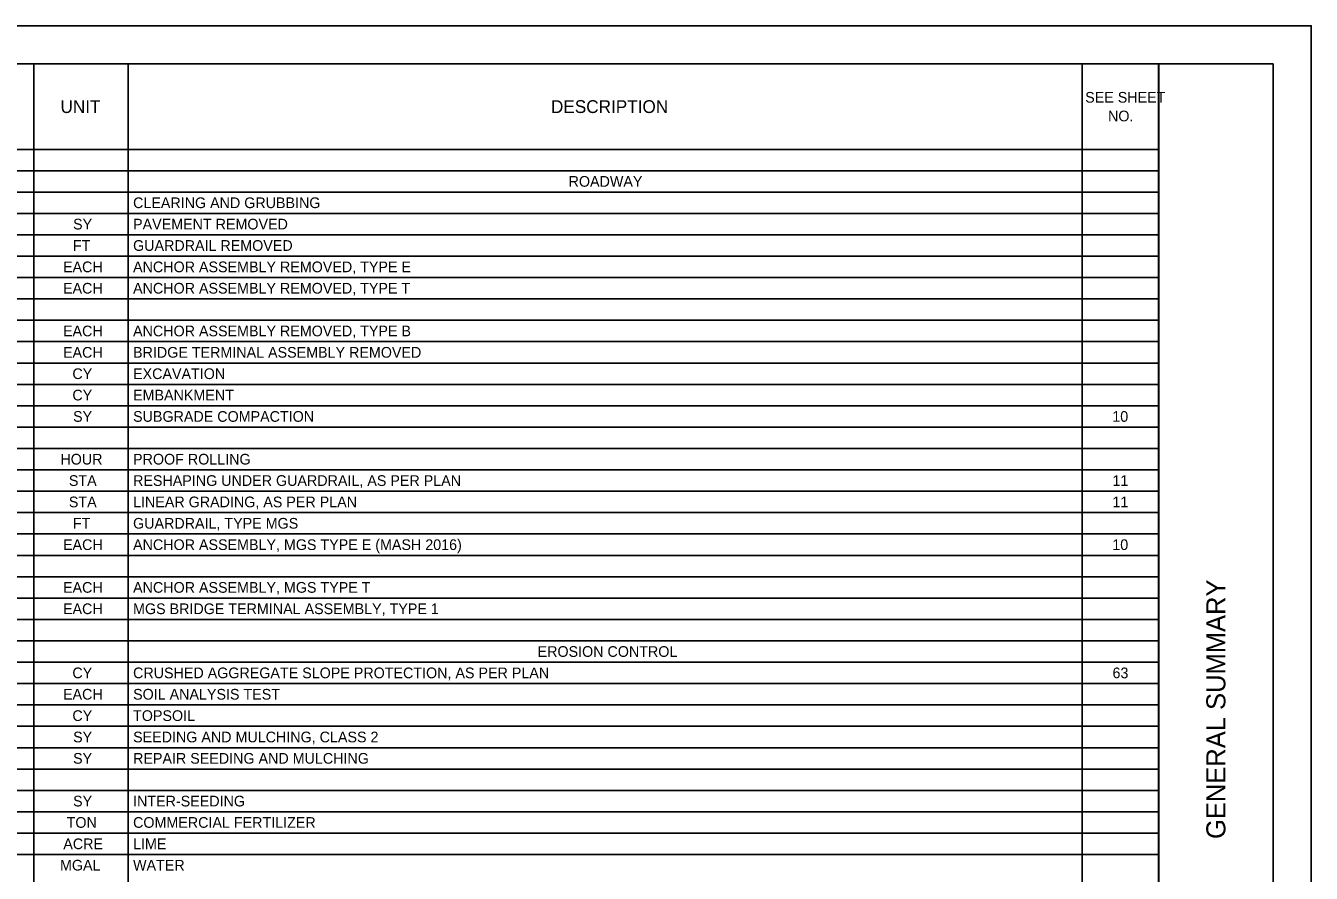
# Model space of a CAD drawing. Extents: x 0 to 34, y 0 to 22.
# Drawn here: x 17.16 to 34, y 10.89 to 22 of the extents above; entities that cross this region are included whole.
import ezdxf

# ---------------------------------------------------------------- set-up
doc = ezdxf.new("R2010")
doc.units = 0
for name, color, linetype in [('SH_Border', 7, 'Continuous'), ('SH_Cut_Line', 7, 'Continuous'), ('SH_Data', 7, 'Continuous'), ('SH_Text', 7, 'Continuous')]:
    doc.layers.add(name, color=color, linetype=linetype)

msp = doc.modelspace()

# ---------------------------------------------------------------- linework, layer by layer
at = {"layer": 'SH_Border'}
msp.add_line((32, 0.5), (32, 21.5), dxfattribs=at)
msp.add_lwpolyline([(1.5, 21.5), (33.5, 21.5), (33.5, 0.5), (1.5, 0.5)], close=True, dxfattribs=at)
at = {"layer": 'SH_Cut_Line'}
msp.add_lwpolyline([(0, 0), (34, 0), (34, 22), (0, 22)], close=True, dxfattribs=at)
at = {"layer": 'SH_Data'}
for p, q in [((1.5, 21.5), (32.004, 21.5)), ((17.262, 21.5), (17.262, 0.5)), ((18.498, 21.5), (18.498, 0.5)), ((30.999, 21.5), (30.999, 0.5)), ((32.004, 21.5), (32.004, 0.5)), ((1.5, 20.38), (32.004, 20.38)), ((1.5, 20.1), (32.004, 20.1)), ((1.5, 19.82), (32.004, 19.82)), ((1.5, 19.54), (32.004, 19.54)), ((1.5, 19.26), (32.004, 19.26)), ((1.5, 18.98), (32.004, 18.98)), ((1.5, 18.7), (32.004, 18.7)), ((1.5, 18.42), (32.004, 18.42)), ((1.5, 18.14), (32.004, 18.14)), ((1.5, 17.86), (32.004, 17.86)), ((1.5, 17.58), (32.004, 17.58)), ((1.5, 17.3), (32.004, 17.3)), ((1.5, 17.02), (32.004, 17.02)), ((1.5, 16.74), (32.004, 16.74)), ((1.5, 16.46), (32.004, 16.46)), ((1.5, 16.18), (32.004, 16.18)), ((1.5, 15.9), (32.004, 15.9)), ((1.5, 15.62), (32.004, 15.62)), ((1.5, 15.34), (32.004, 15.34)), ((1.5, 15.06), (32.004, 15.06)), ((1.5, 14.78), (32.004, 14.78)), ((1.5, 14.5), (32.004, 14.5)), ((1.5, 14.22), (32.004, 14.22)), ((1.5, 13.94), (32.004, 13.94)), ((1.5, 13.66), (32.004, 13.66)), ((1.5, 13.38), (32.004, 13.38)), ((1.5, 13.1), (32.004, 13.1)), ((1.5, 12.82), (32.004, 12.82)), ((1.5, 12.54), (32.004, 12.54)), ((1.5, 12.26), (32.004, 12.26)), ((1.5, 11.98), (32.004, 11.98)), ((1.5, 11.7), (32.004, 11.7)), ((1.5, 11.42), (32.004, 11.42)), ((1.5, 11.14), (32.004, 11.14))]:
    msp.add_line(p, q, dxfattribs=at)

# ---------------------------------------------------------------- texts
msp.add_text('GENERAL SUMMARY', height=0.25, rotation=90, dxfattribs=at).set_placement((32.875, 11.344))
at = {"layer": 'SH_Text'}
for s, height, p in [('SEE SHEET ', 0.14, (31.038, 20.992)), ('UNIT', 0.168, (17.613, 20.856)), ('DESCRIPTION', 0.168, (24.039, 20.856)), ('NO.', 0.14, (31.337, 20.747)), ('ROADWAY', 0.14, (24.27, 19.89)), ('CLEARING AND GRUBBING', 0.14, (18.564, 19.61)), ('SY', 0.14, (17.778, 19.33)), ('PAVEMENT REMOVED', 0.14, (18.564, 19.33)), ('FT', 0.14, (17.776, 19.05)), ('GUARDRAIL REMOVED', 0.14, (18.564, 19.05)), ('EACH', 0.14, (17.646, 18.77)), ('ANCHOR ASSEMBLY REMOVED, TYPE E', 0.14, (18.564, 18.77)), ('EACH', 0.14, (17.646, 18.49)), ('ANCHOR ASSEMBLY REMOVED, TYPE T', 0.14, (18.564, 18.49)), ('EACH', 0.14, (17.646, 17.93)), ('ANCHOR ASSEMBLY REMOVED, TYPE B', 0.14, (18.564, 17.93)), ('EACH', 0.14, (17.646, 17.65)), ('BRIDGE TERMINAL ASSEMBLY REMOVED', 0.14, (18.564, 17.65)), ('CY', 0.14, (17.769, 17.37)), ('EXCAVATION', 0.14, (18.564, 17.37)), ('CY', 0.14, (17.769, 17.09)), ('EMBANKMENT', 0.14, (18.564, 17.09)), ('SY', 0.14, (17.778, 16.81)), ('SUBGRADE COMPACTION', 0.14, (18.564, 16.81)), ('10', 0.14, (31.393, 16.81)), ('HOUR', 0.14, (17.612, 16.25)), ('PROOF ROLLING', 0.14, (18.564, 16.25)), ('STA', 0.14, (17.723, 15.97)), ('RESHAPING UNDER GUARDRAIL, AS PER PLAN', 0.14, (18.564, 15.97)), ('11', 0.14, (31.395, 15.97)), ('STA', 0.14, (17.723, 15.69)), ('LINEAR GRADING, AS PER PLAN', 0.14, (18.564, 15.69)), ('11', 0.14, (31.395, 15.69)), ('FT', 0.14, (17.776, 15.41)), ('GUARDRAIL, TYPE MGS', 0.14, (18.564, 15.41)), ('EACH', 0.14, (17.646, 15.13)), ('ANCHOR ASSEMBLY, MGS TYPE E (MASH 2016)', 0.14, (18.564, 15.13)), ('10', 0.14, (31.393, 15.13)), ('EACH', 0.14, (17.646, 14.57)), ('ANCHOR ASSEMBLY, MGS TYPE T', 0.14, (18.564, 14.57)), ('EACH', 0.14, (17.646, 14.29)), ('MGS BRIDGE TERMINAL ASSEMBLY, TYPE 1', 0.14, (18.564, 14.29)), ('EROSION CONTROL', 0.14, (23.864, 13.73)), ('CY', 0.14, (17.769, 13.45)), ('CRUSHED AGGREGATE SLOPE PROTECTION, AS PER PLAN', 0.14, (18.564, 13.45)), ('63', 0.14, (31.396, 13.45)), ('EACH', 0.14, (17.646, 13.17)), ('SOIL ANALYSIS TEST', 0.14, (18.564, 13.17)), ('CY', 0.14, (17.769, 12.89)), ('TOPSOIL', 0.14, (18.564, 12.89)), ('SY', 0.14, (17.778, 12.61)), ('SEEDING AND MULCHING, CLASS 2', 0.14, (18.564, 12.61)), ('SY', 0.14, (17.778, 12.33)), ('REPAIR SEEDING AND MULCHING', 0.14, (18.564, 12.33)), ('SY', 0.14, (17.778, 11.77)), ('INTER-SEEDING', 0.14, (18.564, 11.77)), ('TON', 0.14, (17.694, 11.49)), ('COMMERCIAL FERTILIZER', 0.14, (18.564, 11.49)), ('ACRE', 0.14, (17.65, 11.21)), ('LIME', 0.14, (18.564, 11.21)), ('MGAL', 0.14, (17.607, 10.93)), ('WATER', 0.14, (18.564, 10.93))]:
    msp.add_text(s, height=height, dxfattribs=at).set_placement(p)

doc.saveas('drawing.dxf')
